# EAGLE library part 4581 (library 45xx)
4-bit ALU
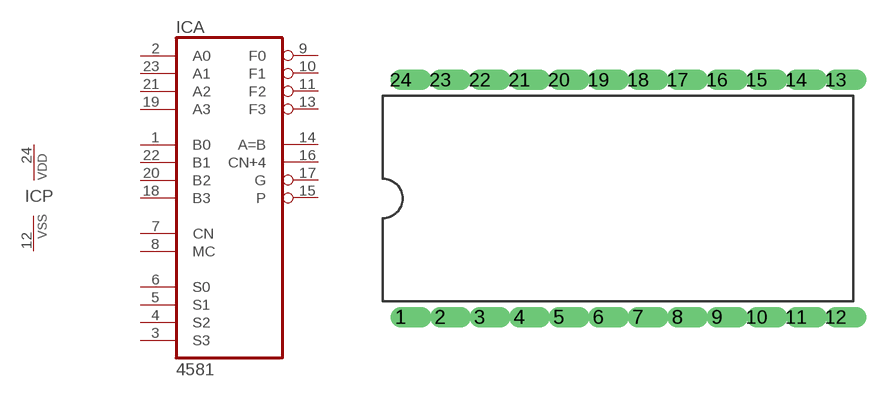
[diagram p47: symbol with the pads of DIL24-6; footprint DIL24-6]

Designator prefix IC; gates A=4581 P=PWRN

## 4581N  [DIL24-6]
1  A:B0  in
2  A:A0  in
3  A:S3  in
4  A:S2  in
5  A:S1  in
6  A:S0  in
7  A:CN  in
8  A:MC  in
9  A:F0  out
10  A:F1  out
11  A:F2  out
12  P:VSS  pwr
13  A:F3  out
14  A:A=B  out
15  A:P  out
16  A:CN+4  out
17  A:G  out
18  A:B3  in
19  A:A3  in
20  A:B2  in
21  A:A2  in
22  A:B1  in
23  A:A1  in
24  P:VDD  pwr

## Footprint DIL24-6 (pad centres in mm)
Dual In Line 0.6 inch
drill 0.813 offset: 1 -13.97,-7.62; 2 -11.43,-7.62; 3 -8.89,-7.62; 4 -6.35,-7.62; 5 -3.81,-7.62; 6 -1.27,-7.62; 7 1.27,-7.62; 8 3.81,-7.62; 9 6.35,-7.62; 10 8.89,-7.62; 11 11.43,-7.62; 12 13.97,-7.62; 13 13.97,7.62; 14 11.43,7.62; 15 8.89,7.62; 16 6.35,7.62; 17 3.81,7.62; 18 1.27,7.62; 19 -1.27,7.62; 20 -3.81,7.62; 21 -6.35,7.62; 22 -8.89,7.62; 23 -11.43,7.62; 24 -13.97,7.62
